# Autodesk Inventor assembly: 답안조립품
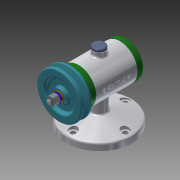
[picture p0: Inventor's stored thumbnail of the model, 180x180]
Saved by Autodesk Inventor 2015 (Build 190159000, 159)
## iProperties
Created: 2018-12
Part Number: 답안조립품
Document SubType Name: Assembly
Designer: now
Author: now
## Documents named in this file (15)
- C:\Users\now\Desktop\481207V1053\답안조립품.iam
- C:\Users\now\Desktop\481207V1053\V벨트풀리.ipt
- C:\Users\now\Desktop\481207V1053\고무캡.ipt
- C:\Users\now\Desktop\481207V1053\너트 M8.ipt
- 너트 M8.ipt
- C:\Users\now\Desktop\481207V1053\뒤커버.ipt
- C:\Users\now\Desktop\481207V1053\베어링 15 x 32 x 9.ipt
- C:\Users\now\Desktop\481207V1053\본체.ipt
- C:\Users\now\Desktop\481207V1053\볼트 M4 x 12.ipt
- C:\Users\now\Desktop\481207V1053\스프링와셔 8.ipt
- C:\Users\now\Desktop\481207V1053\앞커버.ipt
- C:\Users\now\Desktop\481207V1053\오일 실 15 25 7.ipt
- C:\Users\now\Desktop\481207V1053\와셔 8x17.ipt
- C:\Users\now\Desktop\481207V1053\축.ipt
- C:\Users\now\Desktop\481207V1053\키 3 x 3 x 12.ipt
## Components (2 placed, 2 different names)
1. V벨트풀리:1 — 각도:2
2. 고무캡:1
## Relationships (1: Angle 1)
- 각도:2 [Angle]: V벨트풀리:1
